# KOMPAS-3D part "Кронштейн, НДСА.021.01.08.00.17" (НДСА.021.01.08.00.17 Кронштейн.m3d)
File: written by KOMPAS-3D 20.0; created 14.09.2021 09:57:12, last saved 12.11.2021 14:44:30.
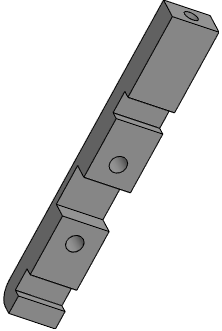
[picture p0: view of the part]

Document properties: Полное имя файла: C:\Users\korychko\Desktop\PLM\НДСА.021.01.08.00.17 Кронштейн.m3d

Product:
- Part/product: Кронштейн  | designation НДСА.021.01.08.00.17
    Материал: Д16  ГОСТ 4784-2019 (density 2800 kg/m3)
    Масса: 0.0243981
    additional columns: <item xmlns="http://appius.ru/pdm" xmlns:xs="http://www.w3.org/2001/XMLSchema" x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; <item xmlns="http://appius.ru/pdm" xmlns:xs="http://www.w3.org/2001/XMLSchema" x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; <item xmlns="http://appius.ru/pdm" xmlns:xs="http://www.w3.org/2001/XMLSchema" x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
    source file: НДСА.021.01.08.00.17 Кронштейн.cdw

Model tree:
1. Эскиз:1
2. Элемент выдавливания:1
     Расстояние 1 = 92
3. Эскиз:2  (with: Элемент выдавливания:1)
4. Элемент выдавливания:2
5. Смещенная плоскость:1
     Расстояние = 5.75
6. Сечение:1
7. Эскиз:7  (with: Элемент выдавливания:1, Сечение:1)
8. Эскиз:8  (with: Сечение:1)
9. Элемент выдавливания:8
     Расстояние 2 = 8.5
10. Условное изображение резьбы:4  (with: Элемент выдавливания:8)  (labels: M6; cil0_24705-2004 coarse)
     Длина резьбы = 8.5; Шаг резьбы = 1; Номинальный диаметр резьбы = 6
11. Подгонка:4  (with: Элемент выдавливания:8)
12. Условное изображение резьбы:5  (with: Элемент выдавливания:8)  (labels: M6; cil0_24705-2004 coarse)
     Длина резьбы = 8.5; Шаг резьбы = 1; Номинальный диаметр резьбы = 6
13. Подгонка:5  (with: Элемент выдавливания:8)
14. Эскиз:9  (with: Элемент выдавливания:1, Подгонка:4, Подгонка:5)
15. Элемент выдавливания:10
     Расстояние 2 = 14
16. Отверстие:1  (with: Элемент выдавливания:1, Сечение:1)  (labels: M5)
     Глубина выреза = 20; Диаметр отверстия = 4.13397; Угол конуса дна = 118; Расстояние 1 = 4.25; Расстояние 2 = 7
17. M5  (with: Элемент выдавливания:1)  (labels: cil0_24705-2004 coarse)
     Длина резьбы = 15; Шаг резьбы = 0.8; Номинальный диаметр резьбы = 5
18. Скругление:1  (with: Элемент выдавливания:1)
     Радиус = 5
19. Эскиз:10  (with: Элемент выдавливания:1)
20. Элемент выдавливания:11  (labels: Д16  ГОСТ 4784-2019)

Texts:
  НДСА.021.01.08.00.17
